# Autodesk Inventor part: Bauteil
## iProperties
Shininess: 64.0
Length Units: 11269
Angle Units: 11279
Time Units: 11290
Mass Units: 11283
Length Display Precision: 3
Angle Display Precision: 2
Compacted: True
Part Number: Bauteil
Document SubType Name: Modeling
Created: 2004-04
Material: Standard
Designer: bchr
Manufacturer: Standard
Standards Organization: Custom
Density: 0.0
Volumn: 0.0
Area: 0.0
PropertySet Name: Model Information
Control State: 0
Master: False
Checked Out: False
Author: bchr
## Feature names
1. Segment Grundform [Extrusion]
2. Wanne [Extrusion]
3. Kuppe [Extrusion]
4. Fuge_Innen_Kuppe
5. Fuge_Innen_Wanne
6. Fuge_Wanne_Außen
7. Ringfuge
8. Semgentmitte
9. Ringfuge_Innen [Revolution]
10. Aushebeöffnung [Revolution]
11. Adjusting [Revolution]
12. Verpressöffnungen [Revolution]
13. Anordnung_Öffnungen [Mirror]
14. Spiegeln10 [Mirror]
